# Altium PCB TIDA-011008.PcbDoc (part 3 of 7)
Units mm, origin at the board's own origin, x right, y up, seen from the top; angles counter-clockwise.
Board outline 252 x 205 mm, 4 copper layers (Top Layer, Inner Layer 1, Inner Layer 2, Bottom Layer), stack 1.926 mm thick; 517 components, 293 nets, 1426 pads, 1855 vias.
Unrouted connection lines stored in the file: 4.
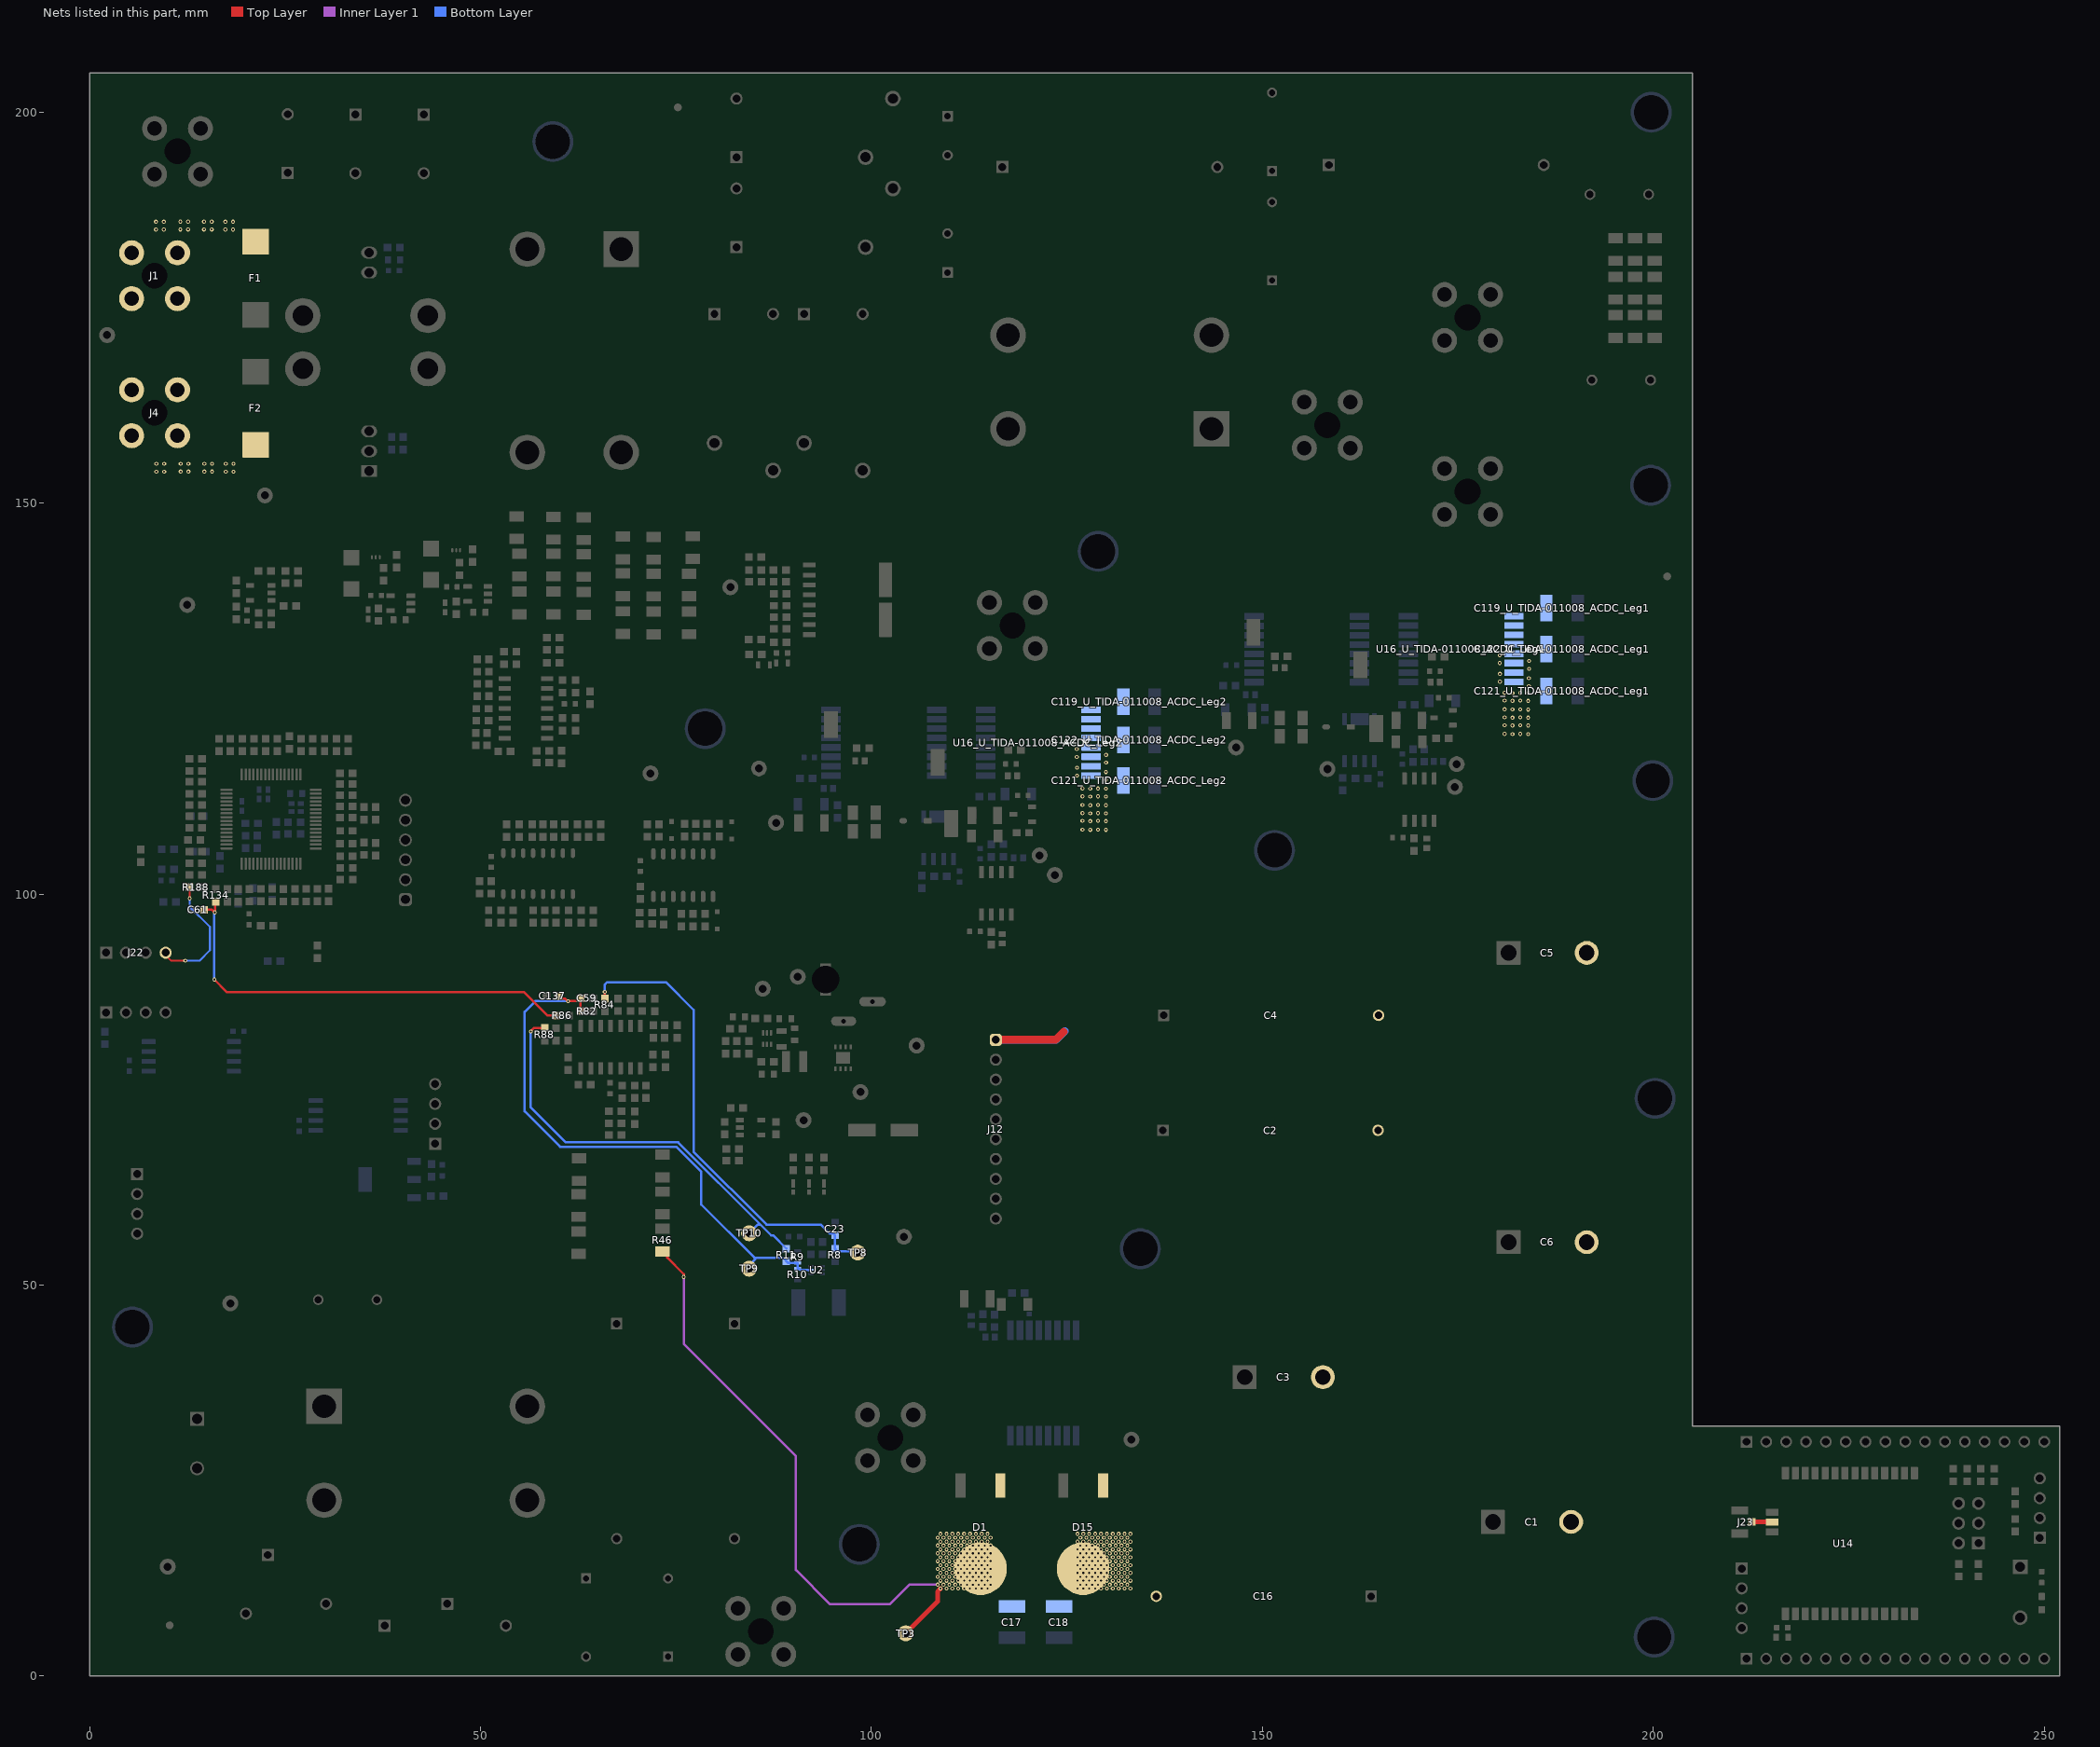
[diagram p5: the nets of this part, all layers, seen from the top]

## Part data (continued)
J16: library part CMP-0054801-2, "Header, 2.54 mm, 6x1, Gold, TH", Color=Black, Manufacturer="Wurth Elektronik", Supplier Part Number 1=732-5319-ND
J17: library part CMP-0054565-2, "Header, 100mil, 3x2, Gold, TH", Color=Black, Current_A=3A, Manufacturer="Sullins Connector Solutions", Supplier Part Number 1=S2011E-03-ND, Voltage_V=1.8kV
J20 J21: library part CMP-0054601-1, "Header, 2.54mm, 16x1, Gold, TH", Color=Black, Current_A=3A, Manufacturer="Sullins Connector Solutions", Supplier Part Number 1=S1011EC-16-ND, Voltage_V=36V
J23: library part CMP-0075320-1, "Receptacle, Ultra Miniature Coaxial, Male Pin, 50 ohm, SMT", Color=Beige, Manufacturer="Hirose Electric Co. Ltd.", Supplier Part Number 1=H122041-ND
K1 K2 K3 K4: library part CMP-0093993-1, "General Purpose Relay SPST-NO (1 Form A) 12VDC Coil Through Hole", Coil Current_A=44.1mA, Coil Power_W=530mW, Coil Resistance=272Ω, Coil Voltage_VDC=12V, Contact Rating_A=20A, Digikey Part Number=39-G5PZ-1A-EDC12-ND, Manufacturer=Omron, Mouser Part Number=653-G5PZ-1A-EDC12, Operating Temperature Range="-40°C to +70°C"
L1 L2 L3: library part CMP-0128165-1, "4.0mH CMC", Manufacturer="Huaihua Yaxin Electronics", Operating Temperature Range="-40°C to +150°C", Test Frequency=10kHz
L5: library part CMP-0056744-1, "Inductor, Drum Core, Ferrite, 10 uH, 0.88 A, 0.276 ohm, SMD", Manufacturer=Bourns, Supplier Part Number 1=SRN3015-100MCT-ND, Value1="0.276 ohm", Value2=0.88A, ValueDisplayed=10uH
L6 L7 L8: library part CMP-0003173-2, "Ferrite Bead, 60 ohm @ 100 MHz, 3 A, 0603", Manufacturer="Wurth Elektronik", Supplier Part Number 1=732-4660-1-ND, Value1="0.04 ohm", Value2=3A, ValueDisplayed="60 ohm"
LBL1: library part CMP-0003625-1, "Thermal Transfer Printable Labels, 0.650\" W x 0.200\" H - 10,000 per roll", Manufacturer=Brady, Supplier Part Number 1=97C5133
Logo1: library part CMP-0074838-1, "Texas Instrument Corporate Signature"
Logo2: library part CMP-0074844-1
Logo3: library part CMP-0074847-1, "FCC_disclaimer"
Logo4: library part CMP-0074769-1
LOGO5: library part CMP-0074837-2, "IEC 61010-1 Hot Surface Warning", Manufacturer="Texas Instruments"
LOGO6: library part CMP-0074835-1, "IEC 61010-1 High Voltage Warning"
MP1 MP2 MP3 MP4 MP5 MP6 MP7 MP8 MP9 MP10 MP11 MP12: library part CMP-0124333-1, "Round Spacer Unthreaded Steel 0.118\" (3.00mm)", Digikey Part Number=732-7087-1-ND, Manufacturer=Wurth, Mouser Part Number=710-9774030960R, Operating Temperature Range="-55°C to +150°C"
Q1 Q2: library part CMP-0067551-1, "MOSFET, N-CH, 30 V, 5.9 A, YJK0003A (PICOSTAR-3)", Alternate Manufacturer=None, Manufacturer="Texas Instruments", Supplier Part Number 1=296-45068-1-ND, Value1="0.033 ohm", Value2="1.9 nC"
R1 R173_U_TIDA-011008_ACDC_Leg1 R173_U_TIDA-011008_ACDC_Leg2 R179_U_TIDA-011008_ACDC_Leg1 R179_U_TIDA-011008_ACDC_Leg2: library part CMP-0025743-4, "RES, 1.0, 5%, 0.1 W, AEC-Q200 Grade 0, 0603", Manufacturer=Vishay-Dale, Power_W=100mW, Supplier Part Number 1=541-1.0GCT-ND, TempCo="200 ppm/C", Tolerance_%=5%, Value2=0.1W, Value_Code=1R00, ValueDisplayed=1.0
R2 R4 R6: library part CMP-0127835-1, "750 V 5 kA Varistor 1 Circuit Through Hole Disc 14mm", Clamping Voltage=1240V, Digikey Part Number=495-B72314S2461K101-ND, Manufacturer=TDK, Mouser Part Number=871-B72314S2461K101, Operating Temperature Range="-40°C to +105°C", ValueDisplayed=260pF, Varistor Voltage=750V, Voltage Tolerance=10%
R3 R175_U_TIDA-011008_ACDC_Leg1 R175_U_TIDA-011008_ACDC_Leg2 R176_U_TIDA-011008_ACDC_Leg1 R176_U_TIDA-011008_ACDC_Leg2 R180_U_TIDA-011008_ACDC_Leg1 R180_U_TIDA-011008_ACDC_Leg2: library part CMP-0023169-5, "RES, 51.0, 1%, 0.1 W, 0603", Manufacturer=Yageo, Power_W=100mW, Supplier Part Number 1=311-51.0HRCT-ND, TempCo="100 ppm/C", Tolerance_%=1%, Value2=0.1W, Value_Code=51R0, ValueDisplayed=51.0
R5 R177_U_TIDA-011008_ACDC_Leg1 R177_U_TIDA-011008_ACDC_Leg2 R181_U_TIDA-011008_ACDC_Leg1 R181_U_TIDA-011008_ACDC_Leg2: library part CMP-0023112-5, "RES, 43.2 k, 1%, 0.1 W, 0603", Manufacturer=Yageo, Power_W=100mW, Supplier Part Number 1=311-43.2KHRCT-ND, TempCo="100 ppm/C", Tolerance_%=1%, Value2=0.1W, Value_Code=43k2, ValueDisplayed=43.2k
R7: library part CMP-0120689-1, "2 mOhms ±1% 5W Chip Resistor 2512 (6432 Metric) Automotive AEC-Q200, Current Sense Metal Element", Digikey Part Number=CSS2H-2512K-2L00FCT-ND, Manufacturer=Bourns, Mouser Part Number=652-CSS2H2512K2L00F, Operating Temperature Range="-55°C to +170°C", Power_W=5W, TempCo=75ppm/°C, Tolerance_%=1%
R8 R11 R26 R31 R32 R33 R49 R86 R87 R178_U_TIDA-011008_ACDC_Leg1 R178_U_TIDA-011008_ACDC_Leg2 R201: library part CMP-0025829-4, "RES, 56, 5%, 0.1 W, AEC-Q200 Grade 0, 0603", Manufacturer=Vishay-Dale, Power_W=100mW, Supplier Part Number 1=541-56GCT-ND, TempCo="200 ppm/C", Tolerance_%=5%, Value2=0.1W, Value_Code=56R0, ValueDisplayed=56
R9 R35: library part CMP-0126304-1, "10 kOhms ±1% 0.1W, 1/10W Chip Resistor 0603 (1608 Metric) Thick Film", Digikey Part Number=541-5136-1-ND, Manufacturer="Vishay Semiconductor", Mouser Part Number=71-CRCW060310K0FKEAC, Operating Temperature Range="-55°C to +155°C", Power_W=100mW, TempCo=100ppm/°C, Tolerance_%=1%
R10 R37: library part CMP-0090742-1, "1 kOhms ±1% 0.1W, 1/10W Chip Resistor 0603 (1608 Metric) Thick Film", Digikey Part Number=541-3949-1-ND, Manufacturer=Vishay, Mouser Part Number=71-CRCW06031K00FKEAC, Operating Temperature Range="-55°C to +155°C", Power_W=100mW, TempCo=100ppm/°C, Tolerance_%=1%
R12 R25: library part CMP-0097004-1, "PTCEL Series 500 V 60 Ohm ±30 % Radial Inrush Current Limiter PTC Thermistor", Digikey Part Number=BC3317-ND, Hold Current=120mA, Manufacturer="Vishay Bccomponents", Mouser Part Number=594-PTCEL13R600LBE, Operating Temperature Range="-40°C to +105°C", Tolerance_%=30%
R13 R17 R24: library part CMP-0096768-1, "5 kA Varistor 1 Circuit Through Hole Disc 17mm", Clamping Voltage=730V, Digikey Part Number=118-ISOM5-275-B-L2-ND, Manufacturer=Bourns, Mouser Part Number=652-ISOM5-275-B-L2, Operating Temperature Range="-40°C to +125°C", ValueDisplayed=40pF
R14 R15 R16 R18 R19 R20 R21 R22 R23: library part CMP-0017399-3, "RES, 169 k, 1%, 0.25 W, AEC-Q200 Grade 0, 1206", Manufacturer=Panasonic, Power_W=250mW, Supplier Part Number 1=P169KFCT-ND, TempCo="100 ppm/C", Tolerance_%=1%, Value2=0.25W, Value_Code=169k
R27 R34: library part CMP-0025882-3, "RES, 100, 5%, 0.25 W, AEC-Q200 Grade 0, 0603", Manufacturer=Rohm, Power_W=250mW, Supplier Part Number 1=RHM100DCT-ND, TempCo="200 ppm/C", Tolerance_%=5%, Value2=0.25W, Value_Code=100R, ValueDisplayed=100
R28 R36 R92 R93 R128 R129 R130 R131 R144 R156 R157 R190 R191: library part CMP-0025945-3, "RES, 10 k, 5%, 0.1 W, 0603", Manufacturer="Samsung Electro-Mechanics", Power_W=100mW, Supplier Part Number 1=1276-5086-1-ND, TempCo="100 ppm/C", Tolerance_%=5%, Value2=0.1W, Value_Code=10k0, ValueDisplayed=10k
R29 R30: library part CMP-0025886-5, "RES, 10 k, 5%, 0.1 W, 0603", Manufacturer=Yageo, Power_W=100mW, Supplier Part Number 1=311-10KGRCT-ND, TempCo="100 ppm/C", Tolerance_%=5%, Value2=0.1W, Value_Code=10k0, ValueDisplayed=10k
R38 R50: library part CMP-0023404-3, "RES, 10.0 k, 0.1%, 0.1 W, 0603", Manufacturer="Susumu Co Ltd", Power_W=100mW, Supplier Part Number 1=RG16P10.0KBCT-ND, TempCo="25 ppm/C", Tolerance_%=0.1%, Value2=0.1W, Value_Code=10k0, ValueDisplayed=10.0k
R39 R40: library part CMP-0084243-1, "RES, 100, 1%, 0.25 W, AEC-Q200 Grade 0, 0603", Manufacturer=Vishay-Dale, Power_W=250mW, TempCo="100 ppm/C", Tolerance_%=1%, Value2=0.25W, Value_Code=100R, ValueDisplayed=100
R41 R42 R54: library part CMP-0023188-5, "RES, 56.0, 1%, 0.1 W, 0603", Manufacturer=Yageo, Power_W=100mW, Supplier Part Number 1=311-56.0HRCT-ND, TempCo="100 ppm/C", Tolerance_%=1%, Value2=0.1W, Value_Code=56R0, ValueDisplayed=56.0
R43 R44 R45: library part CMP-0018431-2, "RES, 680 k, 1%, 0.25 W, 1206", Manufacturer="Yageo America", Power_W=250mW, Supplier Part Number 1=311-680KFRCT-ND, TempCo="100 ppm/C", Tolerance_%=1%, Value2=0.25W, Value_Code=680k
R46 R47 R48: library part CMP-0018373-2, "RES, 560 k, 1%, 0.25 W, 1206", Manufacturer="Yageo America", Power_W=250mW, Supplier Part Number 1=311-560KFRCT-ND, TempCo="100 ppm/C", Tolerance_%=1%, Value2=0.25W, Value_Code=560k
R51 R52 R55 R56 R57 R79 R80 R81 R101 R102 R194 R196 R197 R198: library part CMP-0023337-3, "RES, 10.0 k, 1%, 0.1 W, 0603", Manufacturer="Vishay Draloric", Power_W=100mW, Supplier Part Number 1=541-1784-1-ND, TempCo="100 ppm/C", Tolerance_%=1%, Value2=0.1W, Value_Code=10k0, ValueDisplayed=10.0k
R53: library part CMP-0022751-4, "RES, 10.0, 1%, 0.1 W, 0603", Manufacturer=Yageo, Power_W=100mW, Supplier Part Number 1=311-10.0HRCT-ND, TempCo="100 ppm/C", Tolerance_%=1%, Value2=0.1W, Value_Code=10R0, ValueDisplayed=10.0
R58 R59 R60 R61 R62 R63 R64 R65 R66 R70 R71 R72 R73 R74 R75 R76 R77 R78: library part CMP-0018027-2, "RES, 1.00 M, 1%, 0.25 W, 1206", Manufacturer="Yageo America", Power_W=250mW, Supplier Part Number 1=311-1.00MFRCT-ND, TempCo="100 ppm/C", Tolerance_%=1%, Value2=0.25W, Value_Code=1M00, ValueDisplayed=1.00M
R67 R68 R69 R195: library part CMP-0023286-5, "RES, 80.6, 1%, 0.1 W, 0603", Manufacturer=Yageo, Power_W=100mW, Supplier Part Number 1=311-80.6HRCT-ND, TempCo="100 ppm/C", Tolerance_%=1%, Value2=0.1W, Value_Code=80R6, ValueDisplayed=80.6
R82 R83 R84 R85 R88 R89 R90 R91: library part CMP-0022600-4, "RES, 7.32 k, 1%, 0.1 W, AEC-Q200 Grade 0, 0603", Manufacturer=Vishay-Dale, Power_W=100mW, Supplier Part Number 1=541-7.32KHCT-ND, TempCo="100 ppm/C", Tolerance_%=1%, Value2=0.1W, Value_Code=7k32, ValueDisplayed=7.32k
R98: library part CMP-0025933-5, "RES, 5.6 k, 5%, 0.1 W, 0603", Manufacturer=Yageo, Power_W=100mW, Supplier Part Number 1=311-5.6KGRCT-ND, TempCo="100 ppm/C", Tolerance_%=5%, Value2=0.1W, Value_Code=5k60, ValueDisplayed=5.6k
R99: library part CMP-0025877-3, "RES, 1.5 k, 5%, 0.1 W, AEC-Q200 Grade 0, 0603", Manufacturer=Panasonic, Power_W=100mW, Supplier Part Number 1=P1.5KGCT-ND, TempCo="200 ppm/C", Tolerance_%=5%, Value2=0.1W, Value_Code=1k50, ValueDisplayed=1.5k
R100: library part CMP-0025936-5, "RES, 680, 5%, 0.1 W, 0603", Manufacturer=Yageo, Power_W=100mW, Supplier Part Number 1=311-680GRCT-ND, TempCo="100 ppm/C", Tolerance_%=5%, Value2=0.1W, Value_Code=680R, ValueDisplayed=680
R103: library part CMP-0022739-4, "RES, 105 k, 1%, 0.1 W, 0603", Manufacturer=Yageo, Power_W=100mW, Supplier Part Number 1=311-105KHRCT-ND, TempCo="100 ppm/C", Tolerance_%=1%, Value2=0.1W, Value_Code=105k
R104: library part CMP-0025771-4, "RES, 2.7 k, 5%, 0.1 W, AEC-Q200 Grade 0, 0603", Manufacturer=Vishay-Dale, Power_W=100mW, Supplier Part Number 1=541-2.7KGCT-ND, TempCo="200 ppm/C", Tolerance_%=5%, Value2=0.1W, Value_Code=2k70, ValueDisplayed=2.7k
R105: library part CMP-0022691-3, "RES, 20.0 k, 1%, 0.1 W, AEC-Q200 Grade 0, 0603", Manufacturer=Panasonic, Power_W=100mW, Supplier Part Number 1=P20.0KHCT-ND, TempCo="100 ppm/C", Tolerance_%=1%, Value2=0.1W, Value_Code=20k0, ValueDisplayed=20.0k
R106: library part CMP-0022270-4, "RES, 2.10 k, 1%, 0.1 W, AEC-Q200 Grade 0, 0603", Manufacturer=Vishay-Dale, Power_W=100mW, Supplier Part Number 1=541-2.10KHCT-ND, TempCo="100 ppm/C", Tolerance_%=1%, Value2=0.1W, Value_Code=2k10, ValueDisplayed=2.10k
R107 R137 R158 R169 R170: library part CMP-0025696-3, "RES, 4.7 k, 5%, 0.1 W, 0603", Manufacturer=Bourns, Power_W=100mW, Supplier Part Number 1=CR0603-JW-472GLFCT-ND, TempCo="200 ppm/C", Tolerance_%=5%, Value2=0.1W, Value_Code=4k70, ValueDisplayed=4.7k
R108 R111: library part CMP-0025864-4, "RES, 8.2, 5%, 0.1 W, AEC-Q200 Grade 0, 0603", Manufacturer=Vishay-Dale, Power_W=100mW, Supplier Part Number 1=541-8.2GCT-ND, TempCo="200 ppm/C", Tolerance_%=5%, Value2=0.1W, Value_Code=8R20, ValueDisplayed=8.2
R109 R113 R115 R116 R118 R119 R142 R150 R151 R153 R154 R159 R160: library part CMP-0025861-4, "RES, 82, 5%, 0.1 W, AEC-Q200 Grade 0, 0603", Manufacturer=Vishay-Dale, Power_W=100mW, Supplier Part Number 1=541-82GCT-ND, TempCo="200 ppm/C", Tolerance_%=5%, Value2=0.1W, Value_Code=82R0, ValueDisplayed=82
R110 R112 R114 R117 R120 R121 R122 R123 R124 R125 R126 R127 R132 R133 R134 R135 R136 R138 R139 R140 R141 R143 R145 R146 R147 R148 R149 R152 R161 R182 R183 R184 R185 R186 R187 R188 R189 R192 R193 R199 R200 R202: library part CMP-0081973-1, "RES, 0, 0%, 0.25 W, AEC-Q200 Grade 0, 0603", Manufacturer=Vishay-Dale, Power_W=250mW, Supplier Part Number 1=541-2779-1-ND, Tolerance_%=0%, Value2=0.25W, Value_Code=0
R155: library part CMP-0025906-5, "RES, 2.2 k, 5%, 0.1 W, 0603", Manufacturer=Yageo, Power_W=100mW, Supplier Part Number 1=311-2.2KGRCT-ND, TempCo="100 ppm/C", Tolerance_%=5%, Value2=0.1W, Value_Code=2k20, ValueDisplayed=2.2k
R162 R163 R165 R166 R167 R168: library part CMP-0025701-4, "RES, 10 k, 5%, 0.1 W, AEC-Q200 Grade 0, 0603", Manufacturer=Vishay-Dale, Power_W=100mW, Supplier Part Number 1=541-10KGCT-ND, TempCo="200 ppm/C", Tolerance_%=5%, Value2=0.1W, Value_Code=10k0, ValueDisplayed=10k
R164: library part CMP-0123755-1, "0 Ohms Jumper Chip Resistor 0603 (1608 Metric) Moisture Resistant Thick Film", Digikey Part Number=13-RC0603FR-100RLCT-ND, Manufacturer=Yageo, Mouser Part Number=603-RC0603FR-100RL, Operating Temperature Range="-55°C to +155°C", Tolerance_%=1%
R171_U_TIDA-011008_ACDC_Leg1 R171_U_TIDA-011008_ACDC_Leg2 R172_U_TIDA-011008_ACDC_Leg1 R172_U_TIDA-011008_ACDC_Leg2: library part CMP-0018694-3, "RES, 4.7, 5%, 0.75 W, AEC-Q200 Grade 0, 1206", Manufacturer=Vishay-Dale, Power_W=750mW, Supplier Part Number 1=541-4.7UACT-ND, TempCo="200 ppm/C", Tolerance_%=5%, Value2=0.75W, Value_Code=4R70, ValueDisplayed=4.7
R174_U_TIDA-011008_ACDC_Leg1 R174_U_TIDA-011008_ACDC_Leg2: library part CMP-0025834-4, "RES, 5.1, 5%, 0.1 W, AEC-Q200 Grade 0, 0603", Manufacturer=Vishay-Dale, Power_W=100mW, Supplier Part Number 1=541-5.1GCT-ND, TempCo="200 ppm/C", Tolerance_%=5%, Value2=0.1W, Value_Code=5R10, ValueDisplayed=5.1
SW1: library part CMP-0126760-1, "Switch Tactile SPST Rectangular Button PC Pins 0.05A 24VDC 20000Cycle 1.3N Thru-Hole Bulk", Coil Resistance_ohm=50mΩ, Contact Current Rating=50mA, Digikey Part Number=450-1646-ND, Manufacturer="TE Connectivity", Mouser Part Number=506-FSMH, Operating Force=130gf, Operating Temperature Range="-35°C to +85°C"
TP1 TP2 TP3 TP4 TP5 TP6 TP7 TP8 TP9 TP10 TP11 TP12 TP13 TP14 TP20 TP22 TP23 TP24 TP26_U_TIDA-011008_ACDC_Leg1 TP26_U_TIDA-011008_ACDC_Leg2 TP28_U_TIDA-011008_ACDC_Leg1 TP28_U_TIDA-011008_ACDC_Leg2 TP30_U_TIDA-011008_ACDC_Leg1 TP30_U_TIDA-011008_ACDC_Leg2 TP31_U_TIDA-011008_ACDC_Leg1 TP31_U_TIDA-011008_ACDC_Leg2: library part CMP-0055138-2, "Test Point, Miniature, Black, TH", Color=Black, Manufacturer="Keystone Electronics", Supplier Part Number 1=36-5001-ND
TP15_U_TIDA-011008_ACDC_Leg1 TP15_U_TIDA-011008_ACDC_Leg2 TP29_U_TIDA-011008_ACDC_Leg1 TP29_U_TIDA-011008_ACDC_Leg2 TP32_U_TIDA-011008_ACDC_Leg1 TP32_U_TIDA-011008_ACDC_Leg2: library part CMP-0078225-3, "PC Test Point, SMT", Manufacturer="Keystone Electronics", Supplier Part Number 1=36-5017CT-ND
U1 U16_U_TIDA-011008_ACDC_Leg1 U16_U_TIDA-011008_ACDC_Leg2 U18_U_TIDA-011008_ACDC_Leg1 U18_U_TIDA-011008_ACDC_Leg2: library part CMP-0128366-1, Manufacturer="Texas Instruments", Operating Temperature Range=to
U2: library part CMP-0085242-1, "Bidirectional, Precision Low- and High-Side Voltage Output, Current-Sense Amplifier, DRL0006A (SOT-5X3-6)", Alternate Manufacturer="Texas Instruments", Alternate PartNumber=INA185A2IDRLT
U3: library part CMP-0096051-1, Manufacturer="Texas Instruments", Operating Temperature Range=to
U4 U5: library part CMP-0125179-1, "Quad 5-MHz, 15-V/µs high slew-rate, RRIO op amp 14-SOIC -40 to 125", Digikey Part Number=296-53556-1-ND, Input Bias Current=2pA, Input Offset Voltage=0.33mV, Manufacturer="Texas Instruments", Max Dual Supply Voltage=3V, Max Supply Voltage=6V, Min Dual Supply Voltage=900mV, Min Supply Voltage=1.8V, Mouser Part Number=595-TLV9054IDR, Nominal Supply Current=330uA, Operating Temperature Range="-40°C to +125°C", Output Current Per Channel=50mA, Voltage Gain=130dB
U6 U22: library part CMP-0127286-1, Manufacturer="Texas Instruments", Operating Temperature Range=to
U7: library part CMP-0083940-3, "14 V Bidirectional Flat-Clamp Surge Protection Device, DRB0008A (VSON-8)", Alternate Manufacturer="Texas Instruments", Alternate PartNumber=TVS1401DRBT, Operating Temperature Range="-40 to 125 C"
U8: library part CMP-0860516-1, "4.5-V to 17-V Input, 2-A Synchronous Buck Converter, DRL0006A (SOT-5X3-6)", Alternate Manufacturer="Texas Instruments"
U9: library part CMP-0074640-3, "500-mA, Low IQ, Small Size, Low Dropout Regulator, DBV0005A (SOT-23-5)", Alternate Manufacturer="Texas Instruments"
U10: library part CMP-0036760-1, "Single Output LDO, 1 A, Fixed 3.3 V Output, 2 to 5.5 V Input, 4-pin SOT-223 (DCY), -40 to 125 degC, Green (RoHS & no Sb/Br)", Manufacturer="Texas Instruments"
U11: library part CMP-0047248-1, "Hex Buffers And Line Drivers With 3-State Outputs, D0016A, LARGE T&R", F @ Nom Voltage(Max)(Mhz)=28, Generic Part Number=SN74HC365, ICC @ Nom Voltage(Max)(mA)=0.08, Manufacturer="Texas Instruments", Operating Temperature Range(C)="-40 to 85", Rating=Catalog, tpd @ Nom Voltage(Max)(ns)=20, Voltage(Nom)(V)=6
U12: library part CMP-0126583-1, "Real-Time Microcontroller, LQFP64", Frequency_Fixed=160MHz, Manufacturer="Texas Instruments", Max Supply Voltage=3.63V, Min Supply Voltage=1.19V, Operating Temperature Range="-40°C to +125°C"
U13: library part CMP-0047343-1, "Quadruple Bus Buffer Gates With 3-State Outputs, D0014A, LARGE T&R", F @ Nom Voltage(Max)(Mhz)=110, Generic Part Number=SN74LV125A, ICC @ Nom Voltage(Max)(mA)=0.02, Manufacturer="Texas Instruments", Operating Temperature Range(C)="-40 to 125", Rating=Catalog, tpd @ Nom Voltage(Max)(ns)=15.5,9.5,6.5, Voltage(Nom)(V)=2.5,3.3,5
U14: library part CMP-0127891-1, "Wi-Fi 6 & Bluetooth Module", Manufacturer="Silent Smart", Operating Temperature Range=to
U15_U_TIDA-011008_ACDC_Leg1 U15_U_TIDA-011008_ACDC_Leg2: library part CMP-0127257-1, "General-purpose, dual-channel, 1/1 reverse pinout digital isolator 8-SOIC -40 to 125", Digikey Part Number=296-ISO6721RBDRCT-ND, Manufacturer="Texas Instruments", Max Supply Voltage=5.5V, Min Supply Voltage=1.71V, Mouser Part Number=595-ISO6721RBDR, Operating Temperature Range="-40°C to +125°C", Part Number=ISO6721RBDR
U17_U_TIDA-011008_ACDC_Leg1 U17_U_TIDA-011008_ACDC_Leg2: library part CMP-0122473-1, "Automotive ±1.5°C, 3-kVRMS Isolated Temperature Sensor With Analog Output With < 2 Seconds Response Time and 500VRMS Working Voltage", Manufacturer="Texas Instruments", Max Supply Voltage=5.5V, Min Supply Voltage=2.3V, Operating Supply Current=10uA, Operating Temperature Range="-40°C to +150°C"
U19: library part CMP-0081550-1, "Low-Power, Rail-to-Rail In and Out, 1-MHz Operational Amplifier, DBV0005A (SOT-23-5)", Alternate Manufacturer="Texas Instruments", Alternate PartNumber=TLV9001IDBVT
U20: library part CMP-0128209-2, "Current Sensor", Coil Resistance=0.36mΩ, Current Sensitivity=4V/A, Manufacturer=Sinomags, Max Sensing Current=20A, Max Supply Voltage=5.1V, Min Supply Voltage=4.9V, Operating Temperature Range="-40°C to +105°C"
U21_U_TIDA-011008_ACDC_Leg1 U21_U_TIDA-011008_ACDC_Leg2: library part CMP-0074892-1, "100-mA, 30-V, Fixed-Output, Linear-Voltage Regulator, DBZ0003A (SOT-23-3)", Alternate Manufacturer="Texas Instruments", Alternate PartNumber=TLV76050DBZT
U23 U24: library part CMP-0065552-1, "Single-Channel High-Speed Low-Side Gate Driver with Negative Input Voltage Capability (with 4-A Peak Source and Sink)", Manufacturer="Texas Instruments", Max Supply Voltage=18V, Min Supply Voltage=4.5V, Operating Temperature Range="-40°C to +140°C"

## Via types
v1: diameter 0.508, hole 0.254, Top Layer to Bottom Layer, tented both sides, 1852 vias
v2: diameter 1.5/1.5/1.5/1.5 (per signal layer), hole 1, Top Layer to Bottom Layer, 2 vias
v3: diameter 0.508, hole 0.254, Top Layer to Bottom Layer, 1 vias

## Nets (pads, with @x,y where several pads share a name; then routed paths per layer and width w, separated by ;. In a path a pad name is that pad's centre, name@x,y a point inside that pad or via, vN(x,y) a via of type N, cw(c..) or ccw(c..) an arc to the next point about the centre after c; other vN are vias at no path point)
AC_L: F1.2 J1.1
  other v1: 8.5,185 9.495,185 17.368,185 18.364,185 11.602,185.013 12.598,185.013 14.633,185.013 15.628,185.013 8.5,186 9.495,186 11.602,186.013 12.598,186.013 14.633,186.013 15.628,186.013 17.368,186 18.364,186
AC_N: F2.2 J4.1
  other v1: 8.55,154.034 9.546,154.034 17.419,154.034 18.414,154.034 11.653,154.047 12.648,154.047 14.683,154.047 15.678,154.047 8.55,155.034 9.546,155.034 11.653,155.047 12.648,155.047 14.683,155.047 15.678,155.047 17.419,155.034 18.414,155.034
ANT2: J23.1 U14.30 | length 2.6
  Top Layer w0.6: J23.1@212.615,19.705 U14.30@215.22,19.705
CS_Boost: C61.2 R86.2 R134.2 | length 57.6
  Top Layer w0.3: C61.2@14.358,98.277 C61.2@14.635,97.999 15.643,97.999 15.978,97.664 v1(16.035,97.664) 16.035,98.937 R134.2@16.154,99.056 ; v1(15.954,89.082) 17.536,87.5 55.552,87.5 58.569,84.483 R86.2@59.679,84.483
  Bottom Layer w0.3: v1(15.954,89.082) 15.954,97.526 16.035,97.607 v1(16.035,97.664)
CS_Boost+: C23.1 R8.2 R84.2 TP8.1 | length 60.3
  Top Layer w0.3: R84.2@65.904,86.64 v1(65.904,87.5)
  Bottom Layer w0.3: v1(65.904,87.5) 65.904,88.457 66.19,88.743 73.717,88.743 77.25,85.21 77.25,67.07 86.579,57.742 93.526,57.742 94.664,56.604 95.138,56.604 C23.1@95.35,56.392 R8.2@95.35,54.667 95.35,54.642 95.675,54.317 98.095,54.317 TP8.1@98.25,54.162
CS_Boost-: R11.2 R88.2 TP10.1 | length 53.8
  Top Layer w0.3: v1(56.437,82.431) 56.437,82.483 56.817,82.863 R88.2@58.222,82.863
  Bottom Layer w0.3: v1(56.437,82.431) 56.437,72.725 60.892,68.27 75.277,68.27 85.802,57.746 ; TP10.1@84.358,56.642 85.462,57.746 85.802,57.746 ; R11.2@89.125,54.667 89.125,54.692 87.435,56.381 87.166,56.381 85.802,57.746
CS_Boost_ref: C59.1 C137.1 R9.1 R10.2 R11.1 R82.2 TP9.1 U2.5 | length 73.3
  Top Layer w0.3: C137.1@60.021,86.976 60.346,86.651 60.812,86.651 61.148,86.315 v1(61.204,86.315) 61.904,86.315 61.945,86.356 62.481,86.356 C59.1@62.806,86.681 R82.2@62.806,85.05
  Bottom Layer w0.3: v1(61.204,86.315) 57.027,86.315 55.656,84.944 55.656,72.232 60.18,67.708 75.051,67.708 78.25,64.508 78.25,60.291 85.037,53.504 85.17,53.504 ; TP9.1@84.358,52.109 84.358,52.558 85.17,53.37 85.17,53.504 ; U2.5@92.26,51.942 90.942,51.942 90.775,52.109 R10.2@90.575,52.109 R9.1@90.575,52.859 89.333,52.859 R11.1@89.125,53.067 89.125,53.092 88.712,53.504 85.17,53.504
DAC_A: J22.4 R188.2 | length 16
  Top Layer w0.254: J22.4@9.73,92.516 9.73,92.203 10.447,91.487 v1(12.251,91.487) ; R188.2@12.79,100.915 12.814,100.892 v1(12.814,99.458)
  Bottom Layer w0.254: v1(12.251,91.487) 14.062,91.487 15.399,92.824 15.399,95.816 12.814,98.402 v1(12.814,99.458)
DC_Bus+: C1.2 C2.2 C3.2 C4.2 C5.2 C6.2 C16.2 C17.1 C18.1 C119_U_TIDA-011008_ACDC_Leg1.1 C119_U_TIDA-011008_ACDC_Leg2.1 C121_U_TIDA-011008_ACDC_Leg1.1 C121_U_TIDA-011008_ACDC_Leg2.1 C122_U_TIDA-011008_ACDC_Leg1.1 C122_U_TIDA-011008_ACDC_Leg2.1 D1.1 D1.4 D15.1 D15.4 J12.1 R46.1 TP3.1 U16_U_TIDA-011008_ACDC_Leg1.1 U16_U_TIDA-011008_ACDC_Leg1.2 U16_U_TIDA-011008_ACDC_Leg1.3 U16_U_TIDA-011008_ACDC_Leg1.4 U16_U_TIDA-011008_ACDC_Leg1.5 U16_U_TIDA-011008_ACDC_Leg1.6 U16_U_TIDA-011008_ACDC_Leg1.7 U16_U_TIDA-011008_ACDC_Leg1.8 U16_U_TIDA-011008_ACDC_Leg2.1 U16_U_TIDA-011008_ACDC_Leg2.2 U16_U_TIDA-011008_ACDC_Leg2.3 U16_U_TIDA-011008_ACDC_Leg2.4 U16_U_TIDA-011008_ACDC_Leg2.5 U16_U_TIDA-011008_ACDC_Leg2.6 U16_U_TIDA-011008_ACDC_Leg2.7 U16_U_TIDA-011008_ACDC_Leg2.8 | length 94.8
  Top Layer w0.3: R46.1@73.256,54.162 73.606,54.162 73.906,53.862 73.906,53.504 76,51.41 v1(76,51.059)
  Top Layer w0.6: TP3.1@104.393,5.479 108.455,9.541 108.455,10.802 v1(108.849,11.196)
  Top Layer w1: J12.1@115.917,81.372 123.567,81.372 124.61,82.415
  Inner Layer 1 w0.3: v1(76,51.059) 76,42.475 90.351,28.124 90.351,13.569 94.721,9.199 102.358,9.199 104.862,11.703 v1(108.475,11.703)
  Bottom Layer w1: J12.1@115.917,81.372 123.622,81.372 124.75,82.5
  other v1: 109.601,11.196 110.353,11.196 111.105,11.196 111.857,11.196 112.609,11.196 113.361,11.196 114.113,11.196 114.864,11.196 126.361,11.196 127.113,11.196 127.865,11.196 128.617,11.196 129.369,11.196 130.121,11.196 130.873,11.196 131.625,11.196 132.377,11.196 133.128,11.196 109.227,11.703 109.979,11.703 110.73,11.703 111.482,11.703 112.234,11.703 112.986,11.703 113.738,11.703 114.49,11.703 115.242,11.703 126.739,11.703 127.491,11.703 128.243,11.703 128.994,11.703 129.746,11.703 130.498,11.703 131.25,11.703 132.002,11.703 132.754,11.703 108.849,12.196 109.601,12.196 110.353,12.196 111.105,12.196 111.857,12.196 112.609,12.196 113.361,12.196 114.113,12.196 114.864,12.196 126.361,12.196 127.113,12.196 127.865,12.196 128.617,12.196 129.369,12.196 130.121,12.196 130.873,12.196 131.625,12.196 132.377,12.196 133.128,12.196 108.475,12.703 109.227,12.703 109.979,12.703 110.73,12.703 111.482,12.703 112.234,12.703 112.986,12.703 113.738,12.703 114.49,12.703 115.242,12.703 126.739,12.703 127.491,12.703 128.243,12.703 128.994,12.703 129.746,12.703 130.498,12.703 131.25,12.703 132.002,12.703 132.754,12.703 108.849,13.196 109.601,13.196 110.353,13.196 111.105,13.196 111.857,13.196 112.609,13.196 113.361,13.196 114.113,13.196 114.864,13.196 126.361,13.196 127.113,13.196 127.865,13.196 128.617,13.196 129.369,13.196 130.121,13.196 130.873,13.196 131.625,13.196 132.377,13.196 133.128,13.196 108.475,13.703 109.227,13.703 109.979,13.703 110.73,13.703 111.482,13.703 112.234,13.703 112.986,13.703 113.738,13.703 114.49,13.703 115.242,13.703 126.739,13.703 127.491,13.703 128.243,13.703 128.994,13.703 129.746,13.703 130.498,13.703 131.25,13.703 132.002,13.703 132.754,13.703 108.849,14.196 109.601,14.196 110.353,14.196 111.105,14.196 111.857,14.196 112.609,14.196 113.361,14.196 114.113,14.196 114.864,14.196 126.361,14.196 127.113,14.196 127.865,14.196 128.617,14.196 129.369,14.196 130.121,14.196 130.873,14.196 131.625,14.196 132.377,14.196 133.128,14.196 108.475,14.703 109.227,14.703 109.979,14.703 110.73,14.703 111.482,14.703 112.234,14.703 112.986,14.703 113.738,14.703 114.49,14.703 115.242,14.703 126.739,14.703 127.491,14.703 128.243,14.703 128.994,14.703 129.746,14.703 130.498,14.703 131.25,14.703 132.002,14.703 132.754,14.703 108.849,15.196 109.601,15.196 110.353,15.196 111.105,15.196 111.857,15.196 112.609,15.196 113.361,15.196 114.113,15.196 114.864,15.196 126.361,15.196 127.113,15.196 127.865,15.196 128.617,15.196 129.369,15.196 130.121,15.196 130.873,15.196 131.625,15.196 132.377,15.196 133.128,15.196 108.475,15.703 109.227,15.703 109.979,15.703 110.73,15.703 111.482,15.703 112.234,15.703 112.986,15.703 113.738,15.703 114.49,15.703 115.242,15.703 126.739,15.703 127.491,15.703 128.243,15.703 128.994,15.703 129.746,15.703 130.498,15.703 131.25,15.703 132.002,15.703 132.754,15.703 108.849,16.196 109.601,16.196 110.353,16.196 111.105,16.196 111.857,16.196 112.609,16.196 113.361,16.196 114.113,16.196 114.864,16.196 126.361,16.196 127.113,16.196 127.865,16.196 128.617,16.196 129.369,16.196 130.121,16.196 130.873,16.196 131.625,16.196 132.377,16.196 133.128,16.196 108.475,16.703 109.227,16.703 109.979,16.703 110.73,16.703 111.482,16.703 112.234,16.703 112.986,16.703 113.738,16.703 114.49,16.703 115.242,16.703 126.739,16.703 127.491,16.703 128.243,16.703 128.994,16.703 129.746,16.703 130.498,16.703 131.25,16.703 132.002,16.703 132.754,16.703 108.849,17.196 109.601,17.196 110.353,17.196 111.105,17.196 111.857,17.196 112.609,17.196 113.361,17.196 114.113,17.196 114.864,17.196 126.361,17.196 127.113,17.196 127.865,17.196 128.617,17.196 129.369,17.196 130.121,17.196 130.873,17.196 131.625,17.196 132.377,17.196 133.128,17.196 108.475,17.703 109.227,17.703 109.979,17.703 110.73,17.703 111.482,17.703 112.234,17.703 112.986,17.703 113.738,17.703 114.49,17.703 115.242,17.703 126.739,17.703 127.491,17.703 128.243,17.703 128.994,17.703 129.746,17.703 130.498,17.703 131.25,17.703 132.002,17.703 132.754,17.703 108.849,18.196 109.601,18.196 110.353,18.196 111.105,18.196 111.857,18.196 112.609,18.196 113.361,18.196 114.113,18.196 114.864,18.196 126.361,18.196 127.113,18.196 127.865,18.196 128.617,18.196 129.369,18.196 130.121,18.196 130.873,18.196 131.625,18.196 132.377,18.196 133.128,18.196 127.994,108.232 129.994,108.232 126.998,108.26 128.998,108.26 127.994,109.341 129.994,109.341 126.998,109.368 128.998,109.368 127.994,110.341 129.994,110.341 126.998,110.368 128.998,110.368 127.994,111.382 129.994,111.376 126.998,111.41 128.998,111.403 129.994,112.484 127.994,112.491 126.998,112.518 128.998,112.511 127.994,113.491 129.994,113.484 126.998,113.518 128.998,113.511 129.994,114.622 126.312,115.178 129.994,115.622 126.312,116.178 130.018,116.821 126.274,117.558 130.018,117.821 126.274,118.558 181.995,120.468 183.995,120.468 181,120.496 183,120.496 181.995,121.576 183.995,121.576 181,121.604 183,121.604 181.995,122.576 183.995,122.576 181,122.604 183,122.604 181.995,123.618 183.995,123.612 181,123.646 183,123.639 181.995,124.726 183.995,124.72 183,124.747 181,124.754 181.995,125.726 183.995,125.72 181,125.754 183,125.747 184.089,126.618 180.407,127.174 184.089,127.618 180.407,128.174 184.113,128.817 180.369,129.554 184.113,129.817 180.369,130.554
